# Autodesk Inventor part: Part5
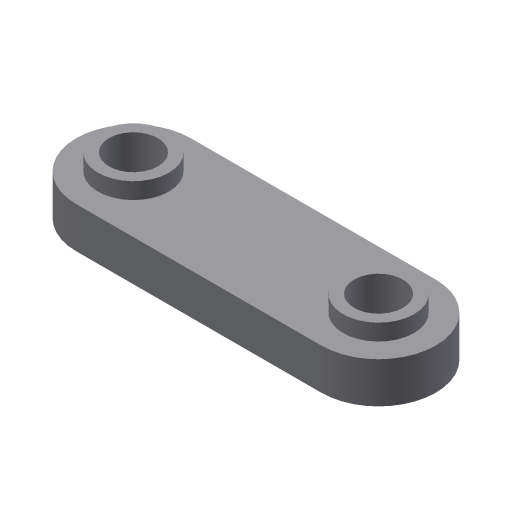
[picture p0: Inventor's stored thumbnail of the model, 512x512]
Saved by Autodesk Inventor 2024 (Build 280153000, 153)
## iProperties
Shininess: 77.0
Length Units: 11269
Angle Units: 11279
Time Units: 11290
Mass Units: 11283
Length Display Precision: 3
Angle Display Precision: 2
Created: 2002-01
Part Number: Part5
Document SubType Name: Modeling
Designer: ***
Density: 1 g/cm^3
Material: Generic
Appearance: Default
Density: 0.0
Volumn: 0.0
Area: 0.0
PropertySet Name: Model Information
Control State: 0
Master: False
Checked Out: False
Author: ***
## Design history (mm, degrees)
sketch "Sketch1"
  geometry: L1 (-33.118, 12.346)-(26.882, 12.361); L2 (-33.111, -15.654)-(26.889, -15.639); C1 r 6 at (-33.114, -1.654); C2 r 6 at (26.886, -1.639); A1 r 14 centre (-33.114, -1.654) between (-33.118, 12.346) and (-33.111, -15.654); A2 r 14 centre (26.886, -1.639) between (26.889, -15.639) and (26.882, 12.361)
  constraints: 4 centre point, 4 end point, 4 point on circle, 4 tangent, 2 coincident, 2 equal radius
  dimensions: "d0" = 60 distance of L1.start L1.end; "d1" = 14 radius of A1; "d2" = 12 diameter of C1
extrude "Extrusion1" new body sketch "Sketch1" distance "d3" = 10; taper "d4" = 0 deg
sketch "Sketch2"
  geometry: C1 r 6 at (26.886, -1.639) reference; C2 r 6 at (-33.114, -1.654) reference; C3 r 8.694 at (-33.114, -1.654); C4 r 8.694 at (26.886, -1.639)
  constraints: 2 centre point, 2 coincident, 1 equal radius
extrude "Extrusion2" join sketch "Sketch2" distance "d5" = 4; taper "d6" = 0 deg
body "Solid1"
